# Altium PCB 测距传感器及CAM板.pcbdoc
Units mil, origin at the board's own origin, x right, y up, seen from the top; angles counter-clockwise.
Board outline 2805 x 2820 mil, 2 copper layers (Top Layer, Bottom Layer); 46 components, 32 nets, 123 pads, 19 vias.
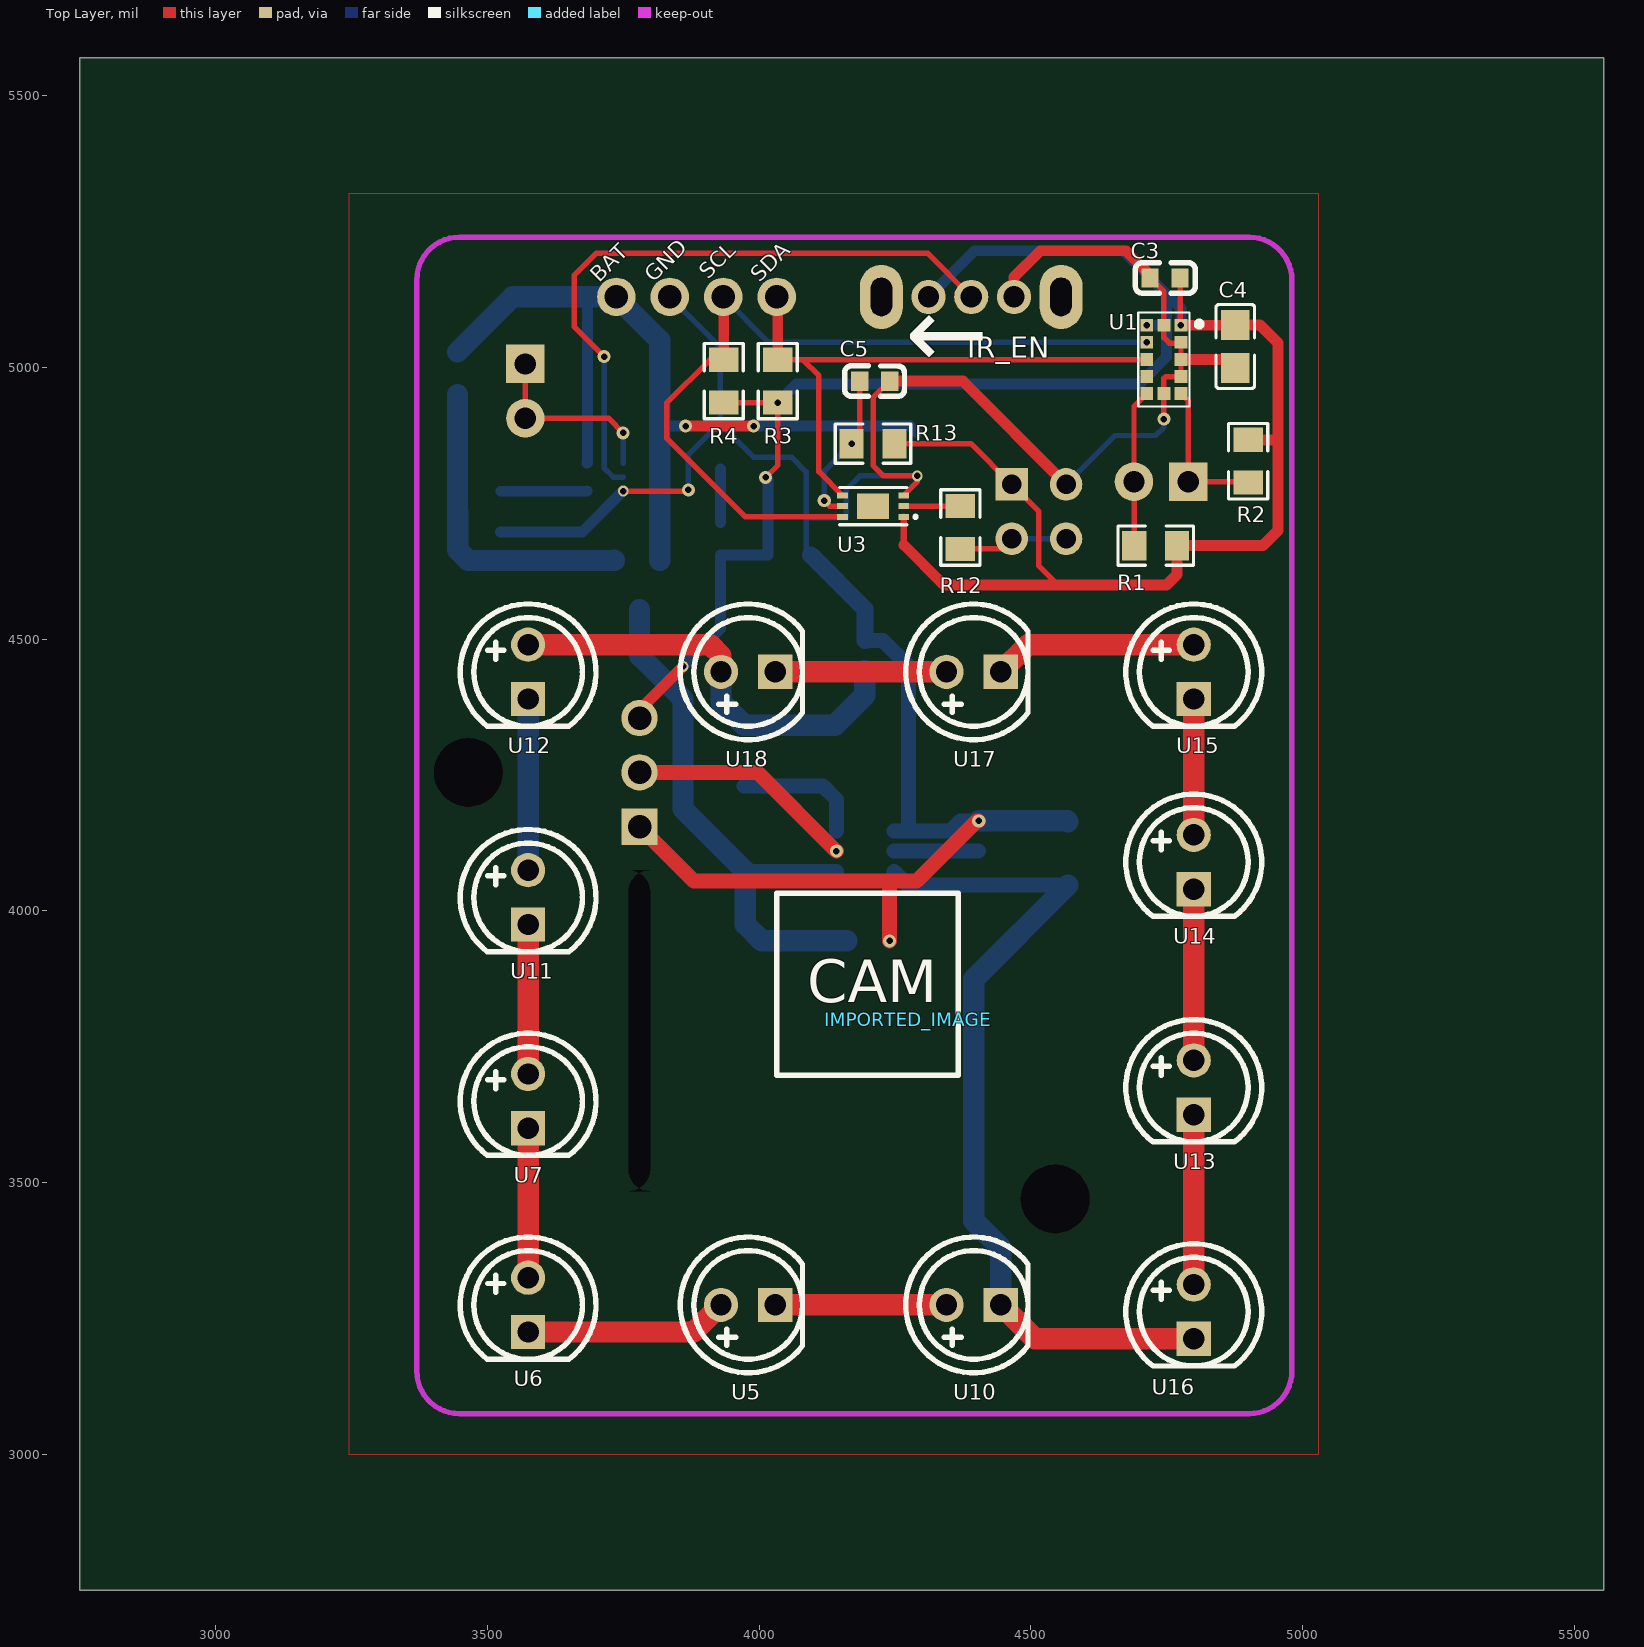
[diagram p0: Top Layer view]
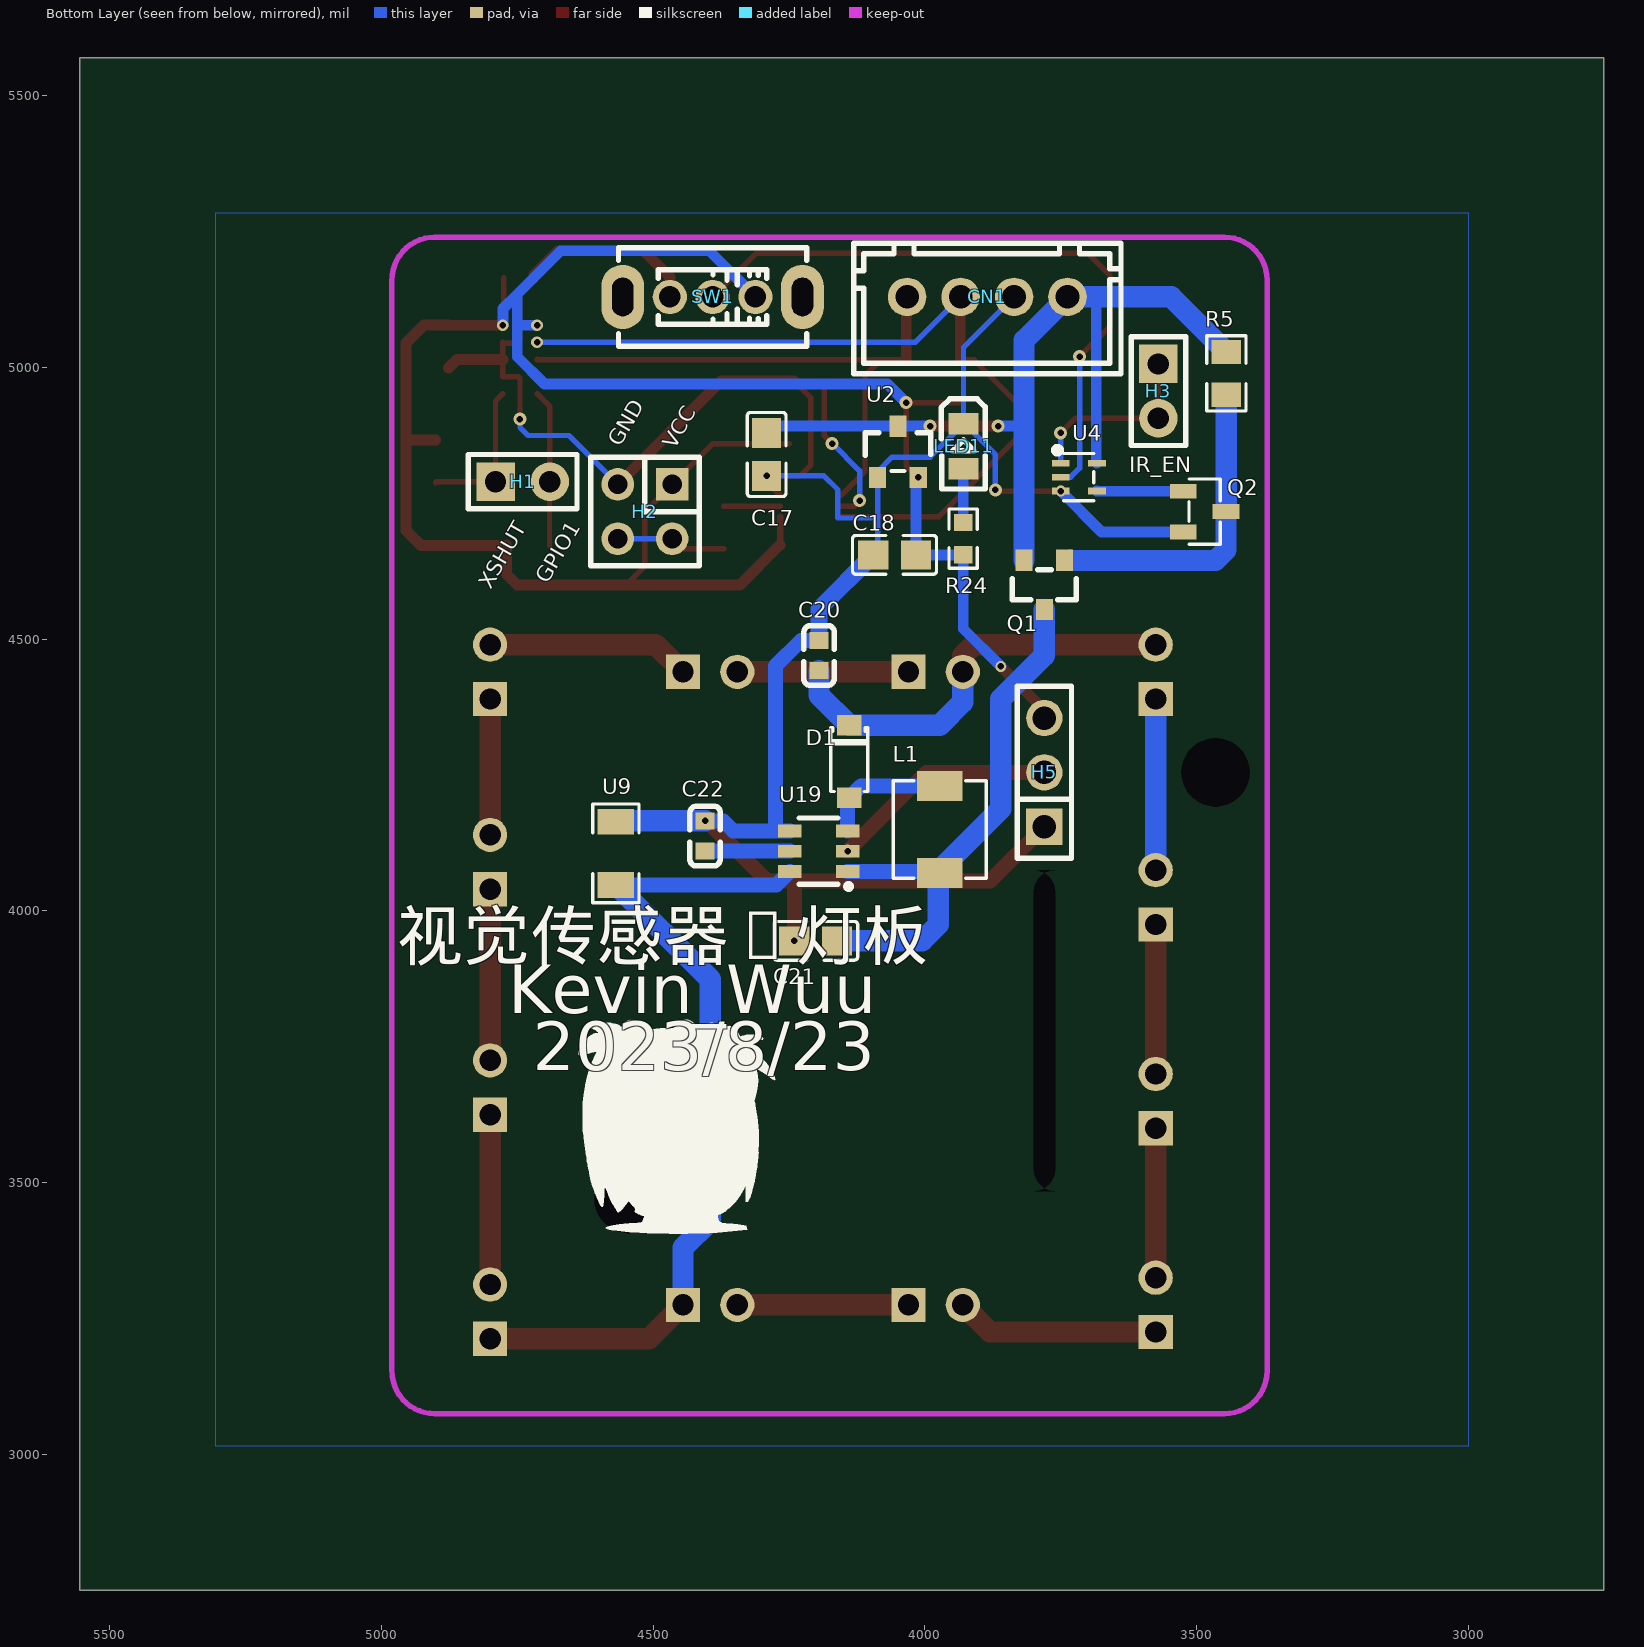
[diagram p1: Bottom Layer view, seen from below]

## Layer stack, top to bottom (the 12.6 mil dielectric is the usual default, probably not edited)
Top Layer: signal copper (thickness not stored)
Dielectric: dielectric 12.6, FR-4, Dk 4.8
Bottom Layer: signal copper (thickness not stored)

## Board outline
5555,2750 2750,2750 2750,5570 5555,5570
cut-out: 4607.99,3470 ccw(c4545,3470) 4482.01,3470 ccw(c4545,3470)
cut-out: 3527.99,4255 ccw(c3465,4255) 3402.01,4255 ccw(c3465,4255)
cut-out: 3799.37,4075 3760,4075 cw(c3760,4035.63) 3799.37,4035.63 3799.37,3523.82 cw(c3760,3523.82) 3760,3484.45 3799.37,3484.45 cw(c3799.37,3523.82) 3760,3523.82 3760,4035.63 cw(c3799.37,4035.63)

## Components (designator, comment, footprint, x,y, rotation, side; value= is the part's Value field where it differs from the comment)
C3 "CC0603KRX7R9BB104" C0603 4747.3,5165 r180 top
C4 "CL21A475KAQNNNE" C0805 4876.43,5038.81 r270 top
C5 "CC0603KRX7R9BB104" C0603 4212.95,4975 r0 top
C17 "CL21B105KBFNNNE" C0805 4291.09,4840 r270 bottom
C18 "CL21B105KBFNNNE" C0805 4055.63,4655.34 r0 bottom
C20 "CL10A105KB8NNNC" C0603 4194.71,4469.88 r270 bottom
C21 "CL21A475KAQNNNE" C0805 4200.81,3945 r0 bottom
C22 "CL10B224KA8NNNC" C0603 4404.28,4138.12 r90 bottom
CN1 "HX25003-4A" CONN-TH_4P-P2.50_HX25003-4A 3885,5130 r180 bottom
D1 "MBR0540T1G" SOD-123_L2.8-W1.8-LS3.7-RD 4139.15,4275 r270 bottom
H1 "HDR-M_2.54_1x2P" HDR-TH_2P-P2.54-V-M-1 4740,4790 r180 bottom
H2 "HDR-M_2.54_2x2" HDR-TH_4P-P2.54-V-M-R2-C2-S2.54-1 4515,4735 r0 bottom
H3 "HDR-M_2.54_1x2P" HDR-TH_2P-P2.54-V-M-1 3570,4956.6 r270 bottom
H5 "HDR-M_2.54_1x3P" HDR-TH_3P-P2.54-V-M 3780,4255 r90 bottom
IMPORTED_IMAGE "IMPORTED_IMAGE" IMPORTED_IMAGE 4275,3800 r0 top
L1 "MWSA0402S-100MT" IND-SMD_L4.4-W4.2 3972.43,4150 r90 bottom
LED11 "NCD0805B2" LED0805-R-RD 3928.7,4855 r270 bottom
Q1 "AO3401A_C15127" SOT-23_L2.9-W1.3-P1.90-LS2.4-BR 3780,4600 r90 bottom
Q2 "MMBT9014C" SOT-23-3_L2.9-W1.3-P1.90-LS2.4-BR 3485,4735 r0 bottom
R1 "RMCF0805FT10K0" R0805 4730,4672.4 r180 top
R2 "RMCF0805FT10K0" R0805 4900.11,4827.62 r270 top
R3 "0805W8F4701T5E" R0805 4034.39,4975 r270 top
R4 "0805W8F4701T5E" R0805 3935,4975 r270 top
R5 "RMCF0805FT10K0" R0805 3445,4989.26 r270 bottom
R12 "RMCF0805FT10K0" R0805 4370.36,4705.62 r270 top
R13 "0805W8F1001T5E" R0805 4209.74,4860 r0 top
R24 "0603WAF4700T5E" R0603 3929.26,4685 r270 bottom
SW1 "SS12D07VG3" SW-TH_SS12D07VG3 4390.5,5130 r0 bottom
U1 "VL53L3CXV0DH/1" OPTO-SMD_12P_VL53L3CXV0DH 4745,5015 r90 top
U2 "XC6206-3.3V" SSOT-3_L2.9-W1.6-P0.95-LS2.8-BR 4049.39,4845 r270 bottom
U3 "BH1750FVI-TR" WSOF-6_L2.6-W1.6-P0.50-TL-EP 4210,4745 r180 top
U4 "SN74LVC1G32DCKR" SOT-353_L2.1-W1.3-P0.65-LS2.3-BR 3716.58,4798.35 r0 bottom
U5 "vsly5940" LED-TH_BD5.8-P2.54-L-RD 3980,3275 r180 top
U6 "vsly5940" LED-TH_BD5.8-P2.54-L-RD 3575,3275 r90 top
U7 "vsly5940" LED-TH_BD5.8-P2.54-L-RD 3575,3650 r90 top
U9 "HoLTT1206-1/4W-2R-1%" R1206 4568.48,4105.95 r270 bottom
U10 "vsly5940" LED-TH_BD5.8-P2.54-L-RD 4395,3275 r180 top
U11 "vsly5940" LED-TH_BD5.8-P2.54-L-RD 3575,4025 r90 top
U12 "vsly5940" LED-TH_BD5.8-P2.54-L-RD 3575,4440 r90 top
U13 "vsly5940" LED-TH_BD5.8-P2.54-L-RD 4800,3675 r90 top
U14 "vsly5940" LED-TH_BD5.8-P2.54-L-RD 4800,4090 r90 top
U15 "vsly5940" LED-TH_BD5.8-P2.54-L-RD 4800,4440 r90 top
U16 "vsly5940" LED-TH_BD5.8-P2.54-L-RD 4800,3262.5 r90 top
U17 "vsly5940" LED-TH_BD5.8-P2.54-L-RD 4395,4440 r180 top
U18 "vsly5940" LED-TH_BD5.8-P2.54-L-RD 3980,4440 r180 top
U19 "TPS61165DBVR" SOT-23-6_L2.9-W1.6-P0.95-LS2.8-BR 4195.31,4110 r180 bottom

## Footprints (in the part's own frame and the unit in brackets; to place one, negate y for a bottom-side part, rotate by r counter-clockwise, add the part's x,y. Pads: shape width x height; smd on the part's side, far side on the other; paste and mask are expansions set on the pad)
C0603 [mm]
  rect 0.8x0.9 smd mask+0.051: 1(-0.7,0) 2(0.7,0)
  silkscreen extent -1.41,-0.71 1.39,0.72
C0805 [mm]
  rect 1.41x1.35 smd paste-100 mask+0.051: 1(-1,0) 2(1,0)
  silkscreen extent -1.96,-0.9 1.96,0.9
CONN-TH_4P-P2.50_HX25003-4A [mm]
  round 1.8 hole 1.1 mask+0.051: 1(-3.75,0) 2(-1.25,0) 3(1.25,0) 4(3.75,0)
  silkscreen extent -6.25,-3.6 6.25,2.51
HDR-TH_2P-P2.54-V-M-1 [mm]
  rect 1.8x1.8 hole 1 mask+0.051: 1(-1.27,0)
  round 1.8 hole 1 mask+0.051: 2(1.27,0)
  silkscreen extent -2.54,-1.27 2.54,1.27
HDR-TH_3P-P2.54-V-M [mm]
  rect 1.7x1.7 hole 1.1 mask+0.051: 1(-2.54,0)
  round 1.7 hole 1.1 mask+0.051: 2(0,0) 3(2.54,0)
  silkscreen extent -4.02,-1.27 4.02,1.27
HDR-TH_4P-P2.54-V-M-R2-C2-S2.54-1 [mil]
  rect 60x60 hole 36 mask+2.01: 1(-50,-50)
  round 60 hole 36 mask+2.01: 2(-50,50) 3(50,-50) 4(50,50)
  silkscreen extent -100,-100 100,100
IMPORTED_IMAGE [mil]
IND-SMD_L4.4-W4.2 [mm]
  rect 1.4x2.12 smd mask+0.051: 1(2.028,0) 2(-2.028,0)
  silkscreen extent -2.28,-2.18 2.28,2.18
LED0805-R-RD [mm]
  rect 1x1.4 smd mask+0.051: 1(1.05,0) 2(-1.05,0)
  silkscreen extent -2.22,-1.04 1.99,1.01
LED-TH_BD5.8-P2.54-L-RD [mm]
  rect 1.6x1.6 hole 1 mask+0.051: 1(-1.27,0)
  round 1.6 hole 1 mask+0.051: 2(1.27,0)
  silkscreen extent -2.54,-3.17 3.17,3.17
OPTO-SMD_12P_VL53L3CXV0DH [mm]
  rect 0.6x0.6 smd paste+0 mask+0.05: 1(1.6,-0.8) 2(0.8,-0.8) 3(0,-0.8) 4(-0.8,-0.8) 5(-1.6,-0.8) 6(-1.6,0) 7(-1.6,0.8) 8(-0.8,0.8) 9(0,0.8) 10(0.8,0.8) 11(1.6,0.8) 12(1.6,0)
  silkscreen extent -2.2,-1.78 2.2,1.2
R0603 [mil]
  rect 31.75x34.02 smd paste-3937.01 mask+2: 1(-29.66,0) 2(29.66,0)
  silkscreen extent -55,-26 55,26
R0805 [mm]
  rect 1.133x1.377 smd paste-100 mask+0.051: 1(-1,0) 2(1,0)
  silkscreen extent -1.76,-0.92 1.76,0.92
R1206 [mil]
  rect 47.54x66.97 smd paste-3937.01 mask+2: 1(-58.22,0) 2(58.22,0)
  silkscreen extent -91,-42 91,42
SOD-123_L2.8-W1.8-LS3.7-RD [mm]
  rect 0.95x1.15 smd mask+0.051: 1(-1.692,0) 2(1.692,0)
  silkscreen extent -1.58,-0.87 1.41,0.87
SOT-23-3_L2.9-W1.3-P1.90-LS2.4-BR [mm]
  rect 1.25x0.7 smd mask+0.051: 1(1,-0.95) 2(1,0.95) 3(-1,0)
  silkscreen extent -0.73,-1.53 0.73,1.53
SOT-23-6_L2.9-W1.6-P0.95-LS2.8-BR [mm]
  rect 1.1x0.6 smd paste+0 mask+0.051: 1(1.35,-0.95) 2(1.35,0) 3(1.35,0.95) 4(-1.35,0.95) 5(-1.35,0) 6(-1.35,-0.95)
  silkscreen extent -0.9,-1.78 1.52,1.55
SOT-23_L2.9-W1.3-P1.90-LS2.4-BR [mm]
  rect 1x0.8 smd mask+0.051: 1(1.15,-0.95) 2(1.15,0.95) 3(-1.15,0)
  silkscreen extent -0.7,-1.5 0.7,1.5
SOT-353_L2.1-W1.3-P0.65-LS2.3-BR [mm]
  rect 0.839x0.315 smd mask+0.051: 1(0.844,-0.65) 2(0.844,0) 3(0.844,0.65) 4(-0.844,0.65) 5(-0.844,-0.65)
  silkscreen extent -0.7,-1.41 1.15,1.1
SSOT-3_L2.9-W1.6-P0.95-LS2.8-BR [mm]
  rect 1x0.8 smd mask+0.051: 1(1.2,-0.95) 2(1.2,0.95) 3(-1.2,0)
  silkscreen extent -0.89,-1.52 0.9,1.52
SW-TH_SS12D07VG3 [mm]
  round 1.6 hole 1 mask+0.051: 1(-2,0) 2(0,0) 3(2,0)
  oval 2x3 hole 1 slot 1.8 at 90 deg mask+0.051: 4(4.2,0) 5(-4.2,0)
  silkscreen extent -4.4,-2.3 4.4,2.3
WSOF-6_L2.6-W1.6-P0.50-TL-EP [mm]
  rect 0.505x0.28 smd mask+0.051: 1(-1.427,0.5) 2(-1.427,0) 3(-1.427,-0.5) 4(1.427,-0.5) 5(1.427,0) 6(1.427,0.5)
  rect 1.5x1.2 smd mask+0.051: 7(0,0)
  silkscreen extent -2.05,-0.88 1.58,0.88

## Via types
v1: diameter 24.02, hole 12.01, Top Layer to Bottom Layer, 13 vias
v2: diameter 21.65, hole 12.01, Top Layer to Bottom Layer, 3 vias
v3: diameter 19.68, hole 12.01, Top Layer to Bottom Layer, 3 vias

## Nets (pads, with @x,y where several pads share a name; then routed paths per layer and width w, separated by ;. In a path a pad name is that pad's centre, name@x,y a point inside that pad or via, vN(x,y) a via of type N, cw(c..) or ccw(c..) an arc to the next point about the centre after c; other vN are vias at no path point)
74LVC_OUT: Q2.1 U4.4 | length 159.1
  Bottom Layer w19.68: Q2.1 3682.98,4772.4 U4.4
$1N3706: Q1.1 Q2.3 R5.2 | length 581.8
  Bottom Layer w39.37: R5.2 3445,4735.63 Q2.3 3445.63,4664.37 3465,4645 3733.27,4645 Q1.1@3733.54,4645.28
$1N5324: R12.1 U3.2 | length 104.2
  Top Layer w10: U3.2 R12.1
$1N5549: C5.1 R13.1 U3.5 | length 285.2
  Top Layer w10: v1(4120,4755) 4130.01,4744.99 U3.5 ; v1(4170.37,4860) 4185.39,4875.02 C5.1
  Bottom Layer w10: v1(4120,4755) 4120,4810 4170,4860 v1(4170.37,4860)
$1N8986: LED11.1 R24.1 | length 99.2
  Bottom Layer w20: LED11.1 3929.26,4813.1 R24.1
$1N27858: U5.1 U10.2 | length 315
  Top Layer w39.37: U5.1 U10.2
$1N27861: U5.2 U6.1 | length 375.7
  Top Layer w39.37: U6.1 3880,3225 U5.2
$1N27864: U13.1 U16.2 | length 312.5
  Top Layer w39.37: U16.2 U13.1
$1N27867: U13.2 U14.1 | length 315
  Top Layer w39.37: U13.2 U14.1
$1N27870: U6.2 U7.1 | length 275
  Top Layer w39.37: U6.2 U7.1
$1N27873: U14.2 U15.1 | length 250
  Top Layer w39.37: U14.2 U15.1
$1N27876: U15.2 U17.1 | length 375.7
  Top Layer w39.37: U17.1 4495,4490 U15.2
$1N27879: U7.2 U11.1 | length 275
  Top Layer w39.37: U7.2 U11.1
$1N27882: U11.2 U12.1 | length 315
  Bottom Layer w39.37: U11.2 U12.1
$1N27885: U17.2 U18.1 | length 315
  Top Layer w39.37: U18.1 U17.2
$1N29363: C22.1 U19.5 | length 156.1
  Bottom Layer w27.56: U19.5 4403.71,4110 C22.1
$1N29460: D1.2 L1.1 U19.3 | length 237.8
  Bottom Layer w27.56: L1.1 4117.69,4229.84 D1.2 4142.15,4205.37 U19.3
$1N29531: C20.2 D1.1 U12.2 U18.2 | length 799.5
  Top Layer w39.37: U12.2 3910,4490 3930,4470 U18.2
  Bottom Layer w39.37: U18.2 3930,4384.32 3972.69,4341.63 D1.1 4194.71,4397.18 C20.2
$1N29572: U9.2 U10.1 U16.1 U19.6 | length 1576.5
  Top Layer w39.37: U10.1 4507.5,3212.5 U16.1
  Bottom Layer w27.56: U19.6 4273.33,4047.73 U9.2
  Bottom Layer w39.37: U10.1 4445,3380 4395,3430 4395,3874.24 U9.2
BATT: C17.1 CN1.4 Q1.2 R5.1 U2.3 U4.5 | length 1637.6
  Top Layer w20: v1(3865,4892.17) v1(3990,4892.17)
  Bottom Layer w19.68: U4.5 3684.4,4825 3684.4,5130
  Bottom Layer w20: 3817.43,4892.17 v1(3865,4892.17) ; v1(3990,4892.17) U2.3@4049.32,4892.17 ; U2.3 4278.22,4892.24 C17.1
  Bottom Layer w39.37: R5.1 3546.37,5130 3684.4,5130 CN1.4 3817.4,5049.96 Q1.2
BU_SW: SW1.2 U4.2 | length 1199.7
  Top Layer w10: v1(3715,5020) 3660,5075 3660,5170 3700,5210 4310.5,5210 SW1.2
  Bottom Layer w10: v1(3715,5020) 3715,4815 3731.65,4798.35 U4.2
DRIVER_EN_PWM: H5.2 U19.2 | length 422.2
  Top Layer w27.56: H5.2 3997.16,4255 v1(4142.15,4110)
GND: C3.2 C4.2 C5.2 C17.2 C18.2 C20.1 C21.2 C22.2 CN1.3 H2.3 H5.1 LED11.2 Q2.2 SW1.3 U1.2 U1.3 U1.4 U1.6 U1.12 U2.1 U3.3 U4.3 U9.1 U19.4 | length 4876.2
  Top Layer w10: v3(3749.82,4772.76) 3867.76,4772.76 v1(3870,4775) ; C5.2 4210,4944.49 4210,4820 4229.37,4800.63 v3(4291.09,4800.63) 4291.09,4789.58 U3.3 ; C3.2 4744.99,5139.75 U1.12 4744.99,5055.01 4755,5045 4775.01,5045 U1.2 U1.3 U1.4 4748.5,4983.5 4745,4980 U1.6 v1(4745,4905)
  Top Layer w20: C5.2 4375,4975 H2.3 ; SW1.3 4469.24,5166.5 4517.74,5215 4675,5215 4719.74,5170.26 C3.2 ; U1.3 4860.87,5015 C4.2
  Top Layer w27.56: H5.1 3880,4055 4240.48,4055 ; v1(4240.18,3945) 4240.18,4054.69 4240.48,4055 ; v1(4404.28,4165.69) 4400.69,4165.69 4290,4055 4240.48,4055
  Bottom Layer w10: CN1.3 3928.7,5037.08 LED11.2 ; v1(3870,4775) 3870,4840 3926.35,4896.35 LED11.2 ; C18.2 4086.79,4663.55 4086.79,4723.15 ; v3(4291.09,4800.63) 4185.63,4800.63 4160.15,4775.15 4160.15,4723.15 4086.79,4723.15 ; H2.3 4655,4875 4730,4875 4745,4890 v1(4745,4905) ; LED11.2 3990.05,4835 4060,4835 4086.79,4808.21 U2.1 4086.79,4723.15
  Bottom Layer w20: Q2.2 3674.66,4697.6 v3(3749.82,4772.76)
  Bottom Layer w27.56: C20.1 4228.17,4497.44 4275,4450.61 4275,4148.24 4274.28,4147.52 ; U19.4 4274.16,4147.4 ; 4274.28,4147.4 4352.53,4147.4 4370.81,4165.69 v1(4404.28,4165.69)
  Bottom Layer w31.5: C18.2 4194.71,4555.63 C20.1
  Bottom Layer w39.37: v1(4404.28,4165.69) 4566.97,4165.69 U9.1
IR_EN: H3.1 H3.2 U4.1 | length 347.1
  Top Layer w10: H3.1 H3.2 3723.4,4906.6 v1(3750,4880)
  Bottom Layer w10: U4.1 3750,4824.12 v1(3750,4880)
LR_GPIO1: H1.2 R1.2 U1.7 | length 289.6
  Top Layer w10: R1.2 4690.63,4789.37 H1.2 4690,4928.51 U1.7
NET1: H2.2 H2.4 R12.2 | length 202.4
  Top Layer w10: R12.2 4446.26,4666.26 H2.2
  Bottom Layer w10: H2.2 H2.4
PWR_IR: C21.1 L1.2 Q1.3 U19.1 | length 1030.1
  Bottom Layer w27.56: L1.2@3974.99,4072.6 U19.1
  Bottom Layer w31.5: L1.2 3974.87,4072.6 3974.99,4072.6 L1.2@3972.43,4075.16
  Bottom Layer w39.37: Q1.3 3780,4470 3860,4390 3860,4187.59 L1.2@3972.43,4075.16 ; L1.2@3974.87,4072.6 3974.87,3975.13 4005,3945 C21.1
SCL: CN1.2 R4.1 U1.10 U3.6 | length 1516.4
  Top Layer w10: R4.1 3909.37,5014.37 3830,4935 3830,4870 3974.68,4725.31 U3.6
  Top Layer w19.68: CN1.2 3935,5129.22 R4.1
  Bottom Layer w10: CN1.2 4017.72,5046.49 v2(4713.51,5046.49)
SDA: CN1.1 R3.1 U1.9 U3.4 | length 1075.7
  Top Layer w10: R3.1 4080.63,5014.37 ; U3.4 4110,4808.48 4110,4985 4080.63,5014.37 ; U1.9 4712.88,5014.37 4080.63,5014.37
  Top Layer w19.68: CN1.1 4034.39,5128.25 R3.1
VCC_3V3: C3.1 C4.1 C18.1 H2.1 H5.3 R1.1 R2.1 R3.2 R4.2 R13.2 R24.2 SW1.1 U1.1 U1.11 U2.2 U3.1 | length 4307.6
  Top Layer w10: R4.2 v1(4034.39,4935.63) 4034.39,4820.16 v1(4011.99,4797.76) ; R13.2 4390,4860 H2.1 4515,4735 4515,4635 4550,4600 ; C3.1 4774.86,5079.62 v2(4776.49,5077.99)
  Top Layer w11.81: 4266.2,4673.8 U3.1
  Top Layer w20: H5.3 3780,4370 v3(3860,4450) ; 4266.2,4673.8 4340,4600 4550,4600 4750,4600 4769.37,4619.37 R1.1 4927.4,4672.4 4955,4700 4955,4866.58 ; v2(4776.49,5077.99) 4876.23,5077.99 C4.1 4921.81,5078.19 4955,5045 4955,4866.58 ; R2.1 4954.59,4866.99 4955,4866.58
  Bottom Layer w20: v3(3860,4450) 3929.26,4519.26 R24.2 C18.1 4016.26,4793.49 v1(4011.99,4797.76) ; v1(4034.39,4935.63) 4068.76,4970 4700,4970 4750,5020 4750,5076.89 ; SW1.1 4396.76,5215 4670,5215 4750,5135 ; v2(4713.51,5077.99) 4748.9,5077.99 4750,5076.89 ; v2(4776.49,5077.99) 4776.49,5108.51 4750,5135 ; 4750,5076.89 4750,5135
XSHUT: H1.1 R2.2 U1.5 | length 278.4
  Top Layer w10: U1.5 4790,4938.51 H1.1 4898.35,4790 R2.2
"": SW1.4 SW1.5 U1.8 U3.7

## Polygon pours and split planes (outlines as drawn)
BATT on Top Layer (solid, remove dead copper, pour order 0): 3245,3000 5030,3000 5030,5320 3245,5320
GND on Bottom Layer (solid, remove dead copper, pour order 1): 3000,3015 5305,3015 5305,5285 3000,5285

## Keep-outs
Board Outline Layer:
  lines w10 net "": 3370,3153.39 ccw(c3448.74,3153.39) 3448.74,3074.65 4901.85,3074.65 ccw(c4901.85,3153.39) 4980.59,3153.39 4980.59,5161.26 ccw(c4901.85,5161.26) 4901.85,5240 3448.74,5240 ccw(c3448.74,5161.26) 3370,5161.26 3370,3153.39

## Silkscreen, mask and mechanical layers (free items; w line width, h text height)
Top Silkscreen Layer:
  lines w10 net "": 4032.33,3697.55 4366.97,3697.55 4366.97,4032.19 4032.33,4032.19 4032.33,3697.55
  text "SCL" at 3906.17,5160.3 h29.2 r45
  text "BAT" at 3706.17,5155.3 h29.2 r45
  text "GND" at 3806.17,5155.3 h29.2 r45
  text "SDA" at 4001.17,5155.3 h29.2 r45
  text "IR_EN" at 4383.36,5018.11 h38.33
  text "←" at 4269.49,4999.69 h133.8
  text "CAM" at 4088.35,3831.64 h77.88
Bottom Silkscreen Layer:
  text "GND" at 4560.1,4852.84 h29.2 r300
  text "VCC" at 4460.1,4847.84 h29.2 r300
  text "IR_EN" at 3624.04,4807.49 h29.2
  text "GPIO1" at 4693.82,4600.61 h29.2 r300
  text "XSHUT" at 4798.82,4590.61 h29.2 r300
  text "视觉传感器&灯板" at 4971.21,3911.46 h89.2
  text "Kevin_Wuu" at 4766.43,3811.46 h89.2
  text "2023/8/23" at 4721.43,3706.46 h89.2
Mechanical Layer:
  circle w1 net "": c4545,3470 r62.99
  circle w1 net "": c3465,4255 r62.99
  lines w1 net "": 3760,3484.45 ccw(c3760,3523.82) 3799.37,3523.82 3799.37,4035.63 ccw(c3760,4035.63) 3760,4075 3799.37,4075 ccw(c3799.37,4035.63) 3760,4035.63 3760,3523.82 ccw(c3799.37,3523.82) 3799.37,3484.45 3760,3484.45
